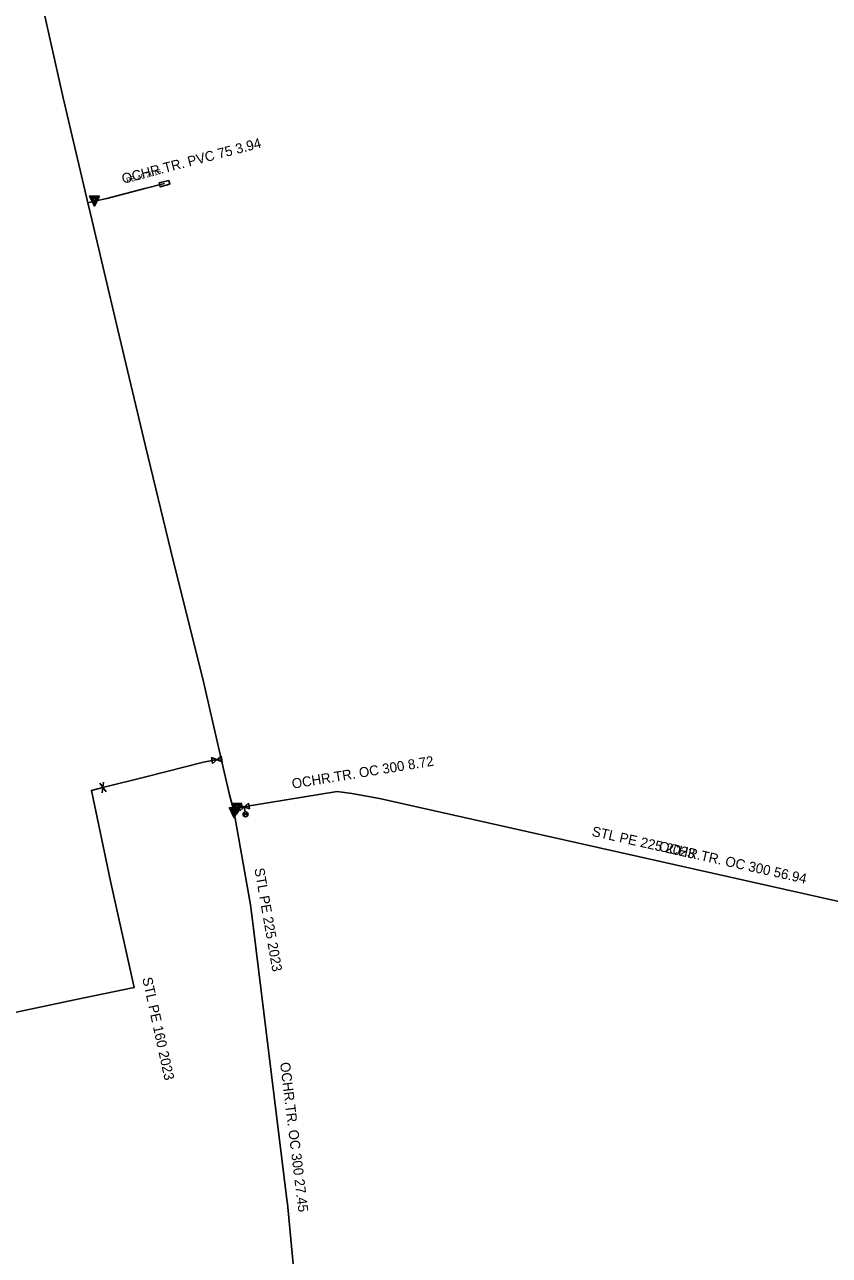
# Model space of a CAD drawing. Extents: x -745298 to -745026, y -1052719 to -1052281.
# Drawn here: x -745233.8 to -745152.9, y -1052567.3 to -1052443.7 of the extents above; entities that cross this region are included whole.
import ezdxf

# ---------------------------------------------------------------- set-up
doc = ezdxf.new("R2010")
doc.units = 0
for name, color, linetype in [('ST OP Chráni_ka - provoz', 7, 'Continuous'), ('ST Úsek p_ípojky - provoz', 7, 'Continuous'), ('ST Úsek plynovodu - provoz', 7, 'Continuous'), ('Vrstva 1', 7, 'Continuous')]:
    doc.layers.add(name, color=color, linetype=linetype)

msp = doc.modelspace()

# ---------------------------------------------------------------- linework, layer by layer
at = {"layer": 'ST OP Chráni_ka - provoz'}
for points in [[(-745225.5, -1052461.14), (-745221.69, -1052460.14)], [(-745215.78, -1052517.78), (-745221.58, -1052519.23)], [(-745214.91, -1052517.59), (-745215.78, -1052517.78)], [(-745221.58, -1052519.23), (-745225.89, -1052520.31)], [(-745210.97, -1052522.13), (-745202.36, -1052520.72)], [(-745198.12, -1052521.42), (-745142.56, -1052533.88)], [(-745210.77, -1052534.47), (-745207.41, -1052561.71)]]:
    msp.add_lwpolyline(points, dxfattribs=at)
at = {"layer": 'ST Úsek p_ípojky - provoz'}
for points in [[(-745226.72, -1052461.4), (-745225.5, -1052461.14), (-745221.69, -1052460.14), (-745219.71, -1052459.64)], [(-745227.4, -1052461.56), (-745226.72, -1052461.4)]]:
    msp.add_lwpolyline(points, dxfattribs=at)
at = {"layer": 'ST Úsek plynovodu - provoz'}
for points in [[(-745232.48, -1052439.35), (-745229.87, -1052451.04), (-745227.4, -1052461.56), (-745227.14, -1052462.68), (-745224.39, -1052474.35), (-745221.62, -1052486.01), (-745218.79, -1052497.65), (-745215.86, -1052509.39), (-745214.01, -1052517.42)], [(-745214.45, -1052517.51), (-745214.91, -1052517.59), (-745215.78, -1052517.78), (-745221.58, -1052519.23), (-745225.89, -1052520.31), (-745227.05, -1052520.6), (-745225.11, -1052529.74), (-745222.76, -1052540.42), (-745228.74, -1052541.66), (-745240.45, -1052544.12), (-745252.09, -1052546.86), (-745253.57, -1052547.2), (-745253.8, -1052547.26)], [(-745214.01, -1052517.42), (-745214.45, -1052517.51)], [(-745214.01, -1052517.42), (-745213.17, -1052521.05), (-745212.78, -1052522.53)], [(-745211.7, -1052522.27), (-745210.97, -1052522.13), (-745202.36, -1052520.72), (-745200.88, -1052520.93), (-745198.12, -1052521.42), (-745142.56, -1052533.88)], [(-745212.78, -1052522.53), (-745212.42, -1052522.43)], [(-745212.42, -1052522.43), (-745211.7, -1052522.27)], [(-745212.78, -1052522.53), (-745212.69, -1052522.85)], [(-745212.69, -1052522.85), (-745211.26, -1052530.96), (-745211.08, -1052532.09), (-745210.98, -1052532.9), (-745210.88, -1052533.66), (-745210.77, -1052534.47)], [(-745210.77, -1052534.47), (-745207.41, -1052561.71), (-745207.36, -1052562.15), (-745207.33, -1052562.49), (-745204.55, -1052592.06), (-745204.5, -1052603.58), (-745204.48, -1052604.43), (-745204.11, -1052612.72), (-745204.78, -1052631.1), (-745204.82, -1052631.6), (-745211.23, -1052677.95), (-745211.47, -1052679.69), (-745215.98, -1052712.7), (-745216.83, -1052718.64), (-745216.92, -1052719.16)]]:
    msp.add_lwpolyline(points, dxfattribs=at)
at = {"layer": 'Vrstva 1'}
for p, q in [((-745214.89, -1052517.89), (-745214.99, -1052517.3)), ((-745214.99, -1052517.3), (-745213.91, -1052517.72)), ((-745214.01, -1052517.13), (-745214.89, -1052517.89)), ((-745213.91, -1052517.72), (-745214.01, -1052517.13)), ((-745225.57, -1052520.75), (-745226.21, -1052519.87)), ((-745225.96, -1052520.84), (-745225.82, -1052519.78)), ((-745211.15, -1052522.47), (-745212.25, -1052522.07)), ((-745212.25, -1052522.07), (-745212.13, -1052522.66)), ((-745212.13, -1052522.66), (-745211.27, -1052521.88)), ((-745211.7, -1052522.27), (-745211.61, -1052522.76)), ((-745211.27, -1052521.88), (-745211.15, -1052522.47))]:
    msp.add_line(p, q, dxfattribs=at)
for points in [[(-745219.27, -1052459.32), (-745219.18, -1052459.71), (-745220.15, -1052459.96), (-745220.24, -1052459.57)], [(-745226.22, -1052460.9), (-745227.22, -1052460.9), (-745226.72, -1052461.9)], [(-745227.06, -1052461), (-745226.72, -1052461.68), (-745226.38, -1052461)], [(-745226.72, -1052461.45), (-745226.54, -1052461.1), (-745226.9, -1052461.1)], [(-745212.19, -1052522.35), (-745213.19, -1052522.35), (-745212.69, -1052523.35)], [(-745213.03, -1052522.45), (-745212.69, -1052523.13), (-745212.35, -1052522.45)], [(-745211.92, -1052521.93), (-745212.92, -1052521.93), (-745212.42, -1052522.93)], [(-745212.76, -1052522.03), (-745212.42, -1052522.71), (-745212.08, -1052522.03)], [(-745212.42, -1052522.48), (-745212.24, -1052522.13), (-745212.6, -1052522.13)], [(-745212.69, -1052522.9), (-745212.51, -1052522.55), (-745212.87, -1052522.55)]]:
    msp.add_lwpolyline(points, close=True, dxfattribs=at)
for centre, radius in [((-745211.56, -1052523.01), 0.249), ((-745211.66, -1052523.02), 0.0614), ((-745211.46, -1052522.98), 0.0614)]:
    msp.add_circle(centre, radius, dxfattribs=at)

# ---------------------------------------------------------------- texts
at = {"layer": 'ST OP Chráni_ka - provoz'}
for s, rotation, p in [('OCHR.TR. PVC 75 3.94', 14.7065, (-745223.85, -1052459.67)), ('OCHR.TR. OC 300 8.72', 9.3004, (-745206.83, -1052520.44)), ('OCHR.TR. OC 300 56.94', 347.3599, (-745170.12, -1052526.67)), ('OCHR.TR. OC 300 27.45', 277.0318, (-745208.1, -1052547.97))]:
    msp.add_text(s, height=1, rotation=rotation, dxfattribs=at).set_placement(p)
at = {"layer": 'ST Úsek p_ípojky - provoz'}
msp.add_text('PE 40 2016', height=0.5, rotation=14.7065, dxfattribs=at).set_placement((-745223.46, -1052459.57))
at = {"layer": 'ST Úsek plynovodu - provoz'}
for s, rotation, p in [('STL PE 225 2023', 347.3599, (-745176.84, -1052525.17)), ('STL PE 225 2023', 279.9999, (-745210.68, -1052528.48)), ('STL PE 160 2023', 282.4095, (-745221.94, -1052539.49))]:
    msp.add_text(s, height=1, rotation=rotation, dxfattribs=at).set_placement(p)

doc.saveas('drawing.dxf')
